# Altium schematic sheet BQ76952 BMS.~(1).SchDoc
size A3; SheetNumber: 9; SheetTotal: 9
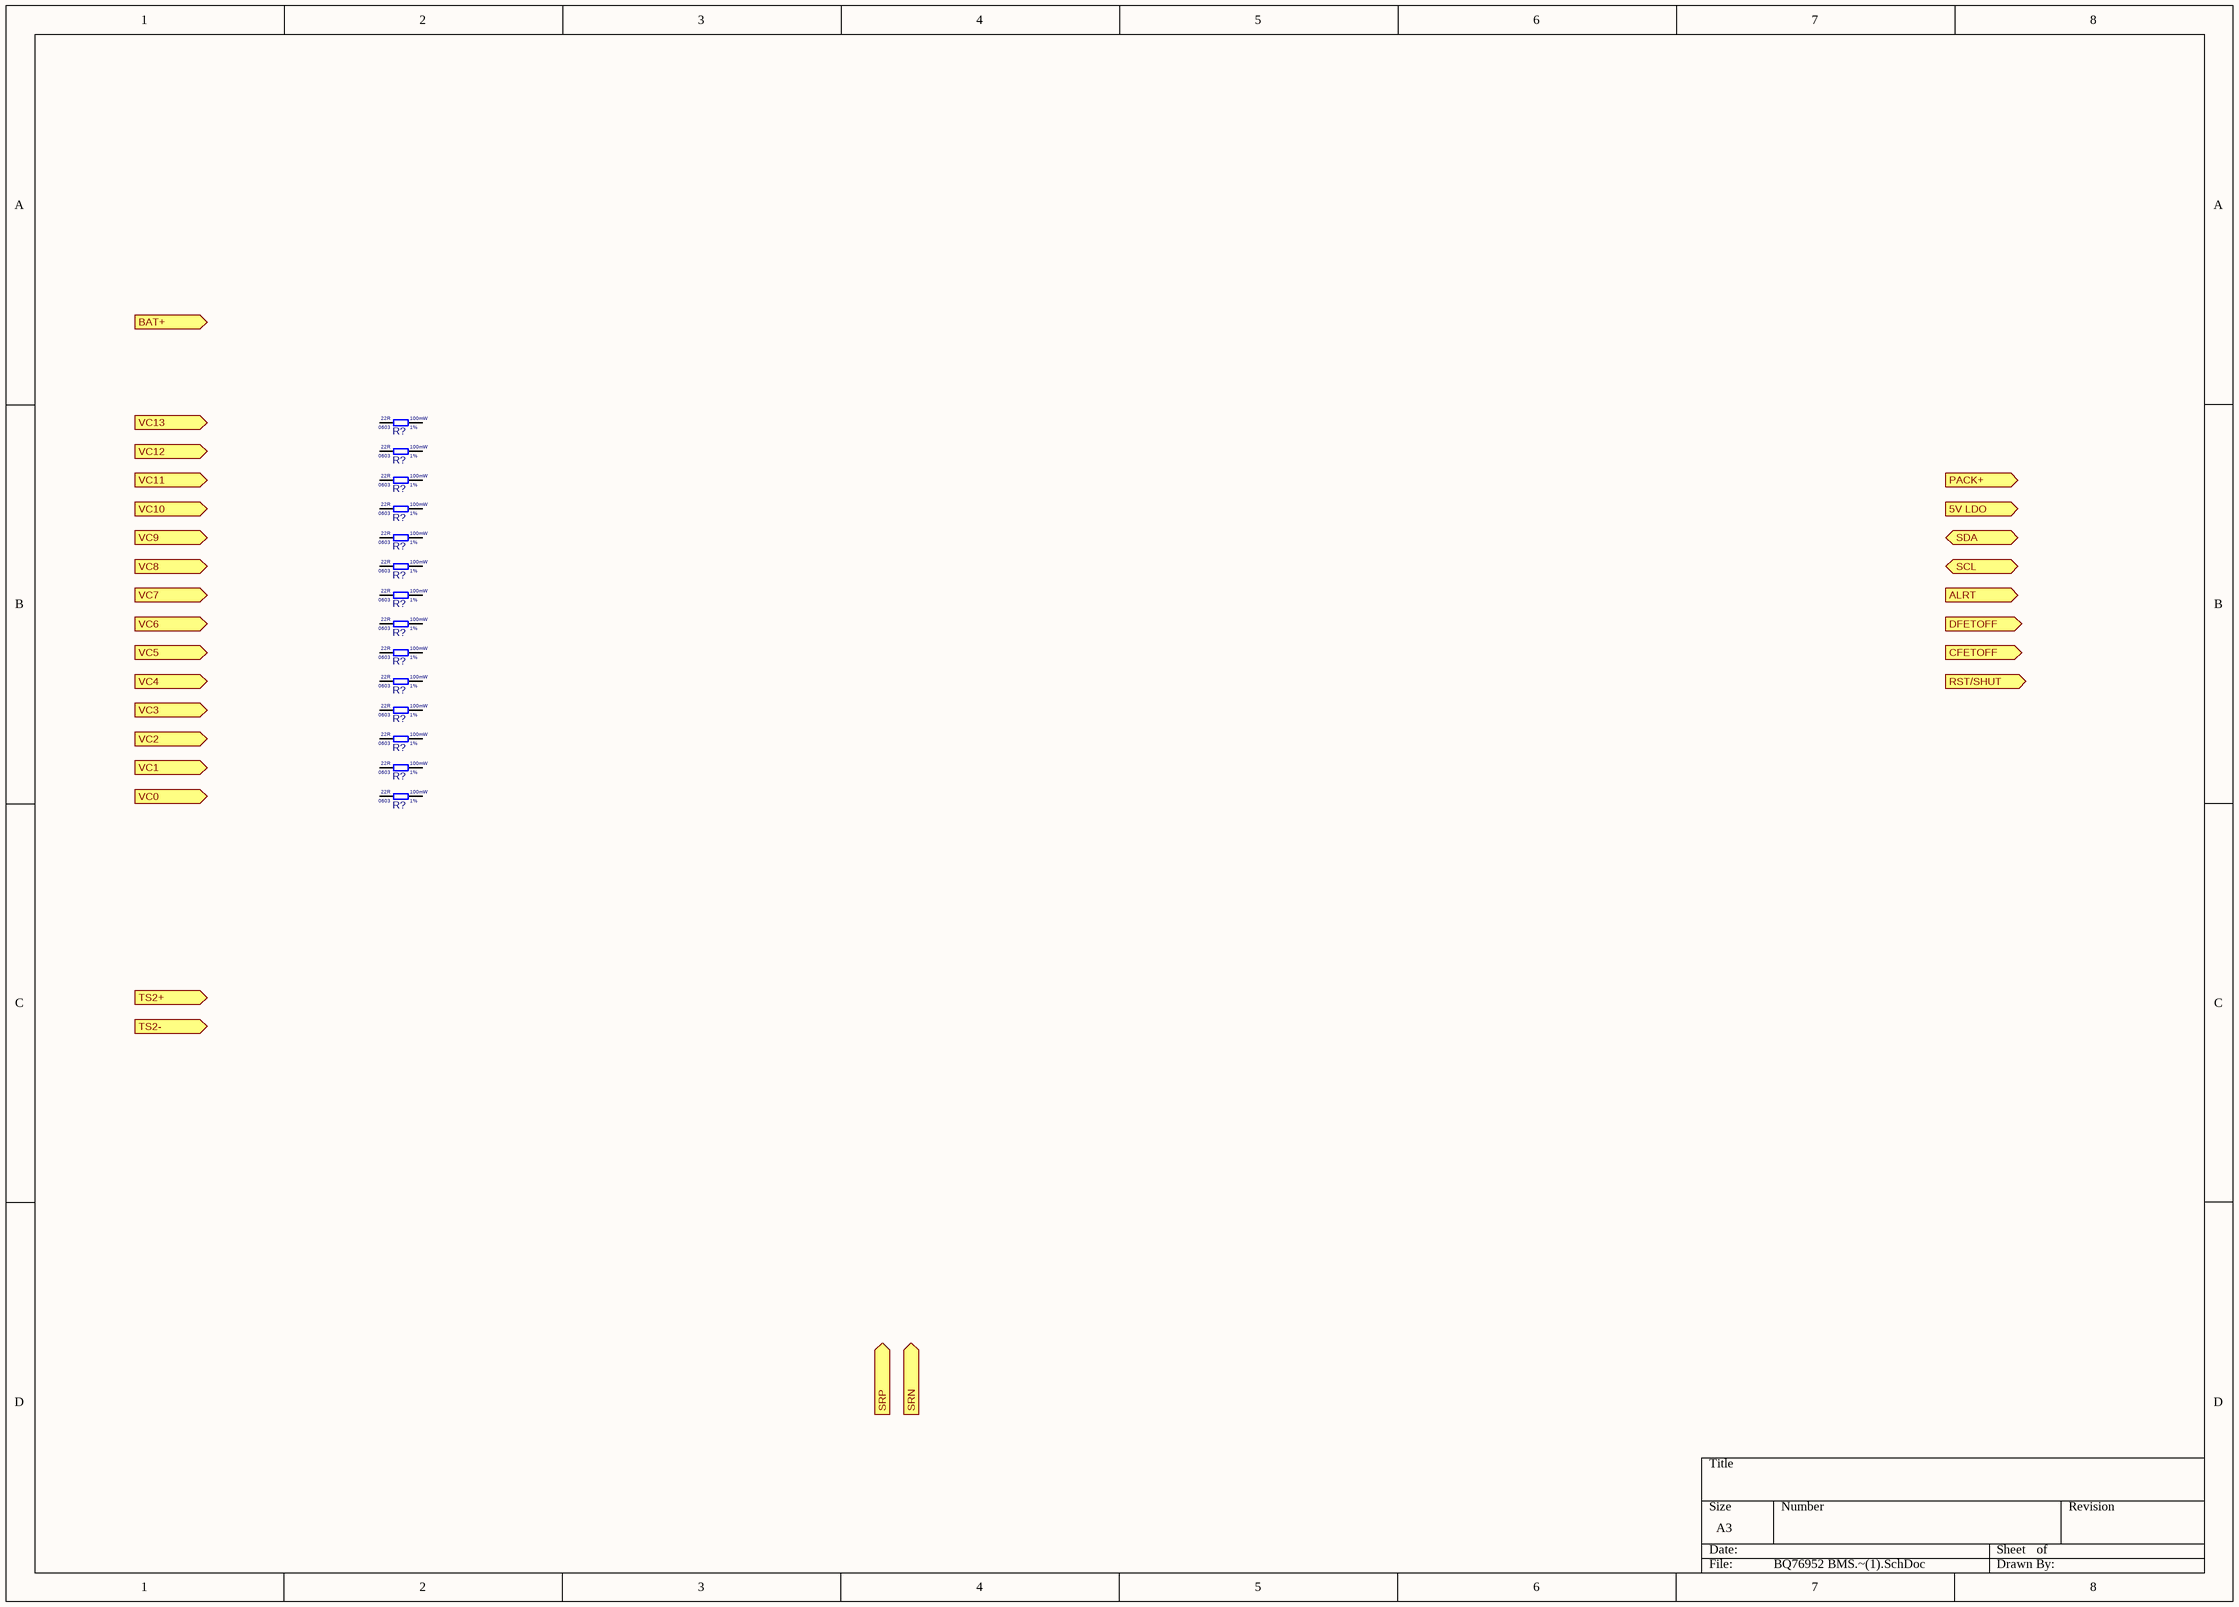
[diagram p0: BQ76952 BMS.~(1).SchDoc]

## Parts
(Parts that share a designator on the sheet are numbered #1, #2 ... from top to bottom, then left to right.)
R?#1  Resistance Tolerance: 1%  Resistance: 22R  Power Rating: 100mW  Case Code (Imperial): 0603  [RES_0603]  (hidden comment: 0603WAF220JT5E)
R?#2  Resistance Tolerance: 1%  Resistance: 22R  Power Rating: 100mW  Case Code (Imperial): 0603  [RES_0603]  (hidden comment: 0603WAF220JT5E)
R?#3  Resistance Tolerance: 1%  Resistance: 22R  Power Rating: 100mW  Case Code (Imperial): 0603  [RES_0603]  (hidden comment: 0603WAF220JT5E)
R?#4  Resistance Tolerance: 1%  Resistance: 22R  Power Rating: 100mW  Case Code (Imperial): 0603  [RES_0603]  (hidden comment: 0603WAF220JT5E)
R?#5  Resistance Tolerance: 1%  Resistance: 22R  Power Rating: 100mW  Case Code (Imperial): 0603  [RES_0603]  (hidden comment: 0603WAF220JT5E)
R?#6  Resistance Tolerance: 1%  Resistance: 22R  Power Rating: 100mW  Case Code (Imperial): 0603  [RES_0603]  (hidden comment: 0603WAF220JT5E)
R?#7  Resistance Tolerance: 1%  Resistance: 22R  Power Rating: 100mW  Case Code (Imperial): 0603  [RES_0603]  (hidden comment: 0603WAF220JT5E)
R?#8  Resistance Tolerance: 1%  Resistance: 22R  Power Rating: 100mW  Case Code (Imperial): 0603  [RES_0603]  (hidden comment: 0603WAF220JT5E)
R?#9  Resistance Tolerance: 1%  Resistance: 22R  Power Rating: 100mW  Case Code (Imperial): 0603  [RES_0603]  (hidden comment: 0603WAF220JT5E)
R?#10  Resistance Tolerance: 1%  Resistance: 22R  Power Rating: 100mW  Case Code (Imperial): 0603  [RES_0603]  (hidden comment: 0603WAF220JT5E)
R?#11  Resistance Tolerance: 1%  Resistance: 22R  Power Rating: 100mW  Case Code (Imperial): 0603  [RES_0603]  (hidden comment: 0603WAF220JT5E)
R?#12  Resistance Tolerance: 1%  Resistance: 22R  Power Rating: 100mW  Case Code (Imperial): 0603  [RES_0603]  (hidden comment: 0603WAF220JT5E)
R?#13  Resistance Tolerance: 1%  Resistance: 22R  Power Rating: 100mW  Case Code (Imperial): 0603  [RES_0603]  (hidden comment: 0603WAF220JT5E)
R?#14  Resistance Tolerance: 1%  Resistance: 22R  Power Rating: 100mW  Case Code (Imperial): 0603  [RES_0603]  (hidden comment: 0603WAF220JT5E)

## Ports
5V LDO (out, see BMS[3A]), ALRT (out, see BMS[3B]), BAT+ (in, see BMS[2A], BMS[1A]), CFETOFF (in, see BMS[3C]), DFETOFF (in, see BMS[3B]), PACK+ (out, see BMS[3A], BMS[8A], Charger BQ25756[1A], CHARGER[1B], Power distribution[3A]), RST/SHUT (in, see BMS[3B]), SCL (bidir, see BMS[3C], BMS[8C]), SDA (bidir, see BMS[3C], BMS[8C]), SRN (in, see BMS[3C]), SRP (in, see BMS[2C]), TS2+ (in, see BMS[2C], BMS[1C]), TS2- (in, see BMS[2C], BMS[1C]), VC0 (in, see BMS[2C], BMS[1C]), VC1 (in, see BMS[2B], BMS[1B]), VC2 (in, see BMS[2B], BMS[1B]), VC3 (in, see BMS[2B], BMS[1B]), VC4 (in, see BMS[2B], BMS[1B]), VC5 (in, see BMS[2B], BMS[1B]), VC6 (in, see BMS[2B], BMS[1B]), VC7 (in, see BMS[2B], BMS[1B]), VC8 (in, see BMS[2B], BMS[1B]), VC9 (in, see BMS[2B], BMS[1B]), VC10 (in, see BMS[2B], BMS[1B]), VC11 (in, see BMS[2B], BMS[1B]), VC12 (in, see BMS[2B], BMS[1B]), VC13 (in, see BMS[2B], BMS[1B])

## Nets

Not connected (* = marked no-connect by the designer): R?#1 1 2; R?#2 1 2; R?#3 1 2; R?#4 1 2; R?#5 1 2; R?#6 1 2; R?#7 1 2; R?#8 1 2; R?#9 1 2; R?#10 1 2; R?#11 1 2; R?#12 1 2; R?#13 1 2; R?#14 1 2

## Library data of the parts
R?#1-R?#14 = 0603WAF220JT5E: Res 22R 0603 1% 100mW 75V; Manufacturer: Uni-Royal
